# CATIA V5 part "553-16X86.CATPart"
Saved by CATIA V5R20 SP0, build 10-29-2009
Part number: 553-16X86
Definition: NONE
Nomenclature: 553-16X86
Source: Unknown
Description: 553-16X86
Bounding box of the stored display mesh (mm): x 0 to 86, y -13 to 13, z -13 to 13
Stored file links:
  C:\Users\Utente\Desktop\IO LAVORO\3D X SITO CF\X SITO\PLASTICA\553\553-16X86.CATPart
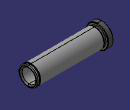
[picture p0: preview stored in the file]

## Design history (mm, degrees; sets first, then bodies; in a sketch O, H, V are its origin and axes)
Body1 "553-16X86" (main body)
  Solid1: solid without history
